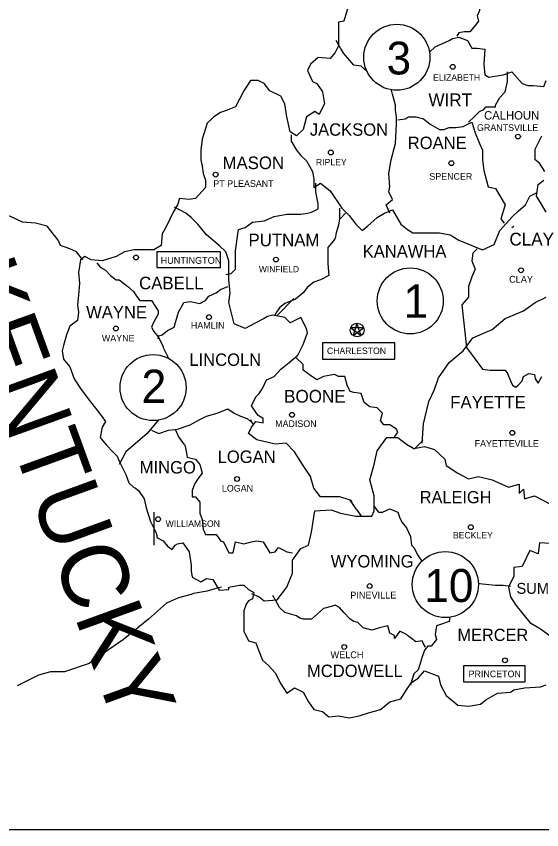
# Model space of a CAD drawing. Extents: x -2.1 to 5.9, y -23.5 to -12.8.
# Drawn here: x 2.655 to 3.484, y -23.135 to -21.85 of the extents above; entities that cross this region are included whole.
import ezdxf

# ---------------------------------------------------------------- set-up
doc = ezdxf.new("R2010")
doc.units = 0
doc.layers.add('Construction Line', color=7, linetype='Continuous')

msp = doc.modelspace()

# ---------------------------------------------------------------- linework, layer by layer
at = {"layer": 'Construction Line'}
for p, q in [((3.1659, -22.1692), (3.1742, -22.161)), ((3.0655, -22.323), (3.0926, -22.2959)), ((3.2023, -22.3421), (3.1822, -22.3421)), ((3.1822, -22.3421), (3.1986, -22.354)), ((3.1921, -22.335), (3.1861, -22.354)), ((3.1861, -22.354), (3.2023, -22.3421)), ((3.1986, -22.354), (3.1921, -22.335)), ((3.2824, -22.5335), (3.2961, -22.5198)), ((2.8714, -22.633), (2.8714, -22.6851)), ((5.62, -23.1348), (-1.8802, -23.1348))]:
    msp.add_line(p, q, dxfattribs=at)
for points in [[(3.3394, -21.7539), (3.3411, -21.759), (3.3394, -21.7695), (3.3479, -21.7712), (3.3578, -21.7746), (3.3666, -21.7865), (3.37, -21.7865), (3.3785, -21.7933), (3.3836, -21.8117), (3.3853, -21.8304), (3.3853, -21.8406), (3.3819, -21.8491), (3.3836, -21.8576), (3.3785, -21.8644), (3.37, -21.8743), (3.3612, -21.8743), (3.353, -21.876), (3.3496, -21.8811)], [(3.1799, -21.829), (3.1714, -21.8576), (3.1629, -21.8593), (3.1629, -21.8882), (3.1629, -21.8967), (3.1578, -21.9069), (3.1496, -21.9168), (3.1309, -21.9151), (3.119, -21.9253), (3.1139, -21.9355), (3.1221, -21.9528), (3.1289, -21.9559), (3.1377, -21.9695), (3.1411, -21.9882), (3.1343, -22.0001), (3.1326, -22.0052), (3.1255, -22.0001), (3.1122, -22.0086), (3.1071, -22.029), (3.0969, -22.0389), (3.0867, -22.0324), (3.0816, -22.0086), (3.0782, -21.9882), (3.0717, -21.9763), (3.0544, -21.9678), (3.0459, -21.9559), (3.036, -21.9511), (3.0241, -21.9511), (3.0136, -21.9678), (3.0003, -21.993), (2.9901, -21.997), (2.9816, -22.0001)], [(3.2088, -21.9378), (3.1989, -21.9287), (3.187, -21.927), (3.1714, -21.9086), (3.1663, -21.9001), (3.1595, -21.8882)], [(3.3063, -21.9064), (3.3156, -21.8984), (3.3377, -21.8882), (3.3428, -21.8848), (3.353, -21.8831), (3.3666, -21.8882), (3.3734, -21.9001), (3.3819, -21.9001), (3.3938, -21.9018), (3.3921, -21.9253), (3.3938, -21.9426), (3.4003, -21.946), (3.4227, -21.9426), (3.4363, -21.9375), (3.453, -21.9559), (3.4615, -21.9593), (3.47, -21.9593), (3.487, -21.961), (3.4904, -21.9511)], [(3.3683, -22.0171), (3.3768, -22.0086), (3.3853, -22.0001), (3.3921, -21.997), (3.3952, -21.993), (3.4105, -21.993), (3.4105, -21.9902), (3.4176, -21.978), (3.4261, -21.9695), (3.4295, -21.9528), (3.4295, -21.9375)], [(3.2442, -22.161), (3.238, -22.1477), (3.2479, -22.1392), (3.2425, -22.1273), (3.2442, -22.1191), (3.2425, -22.0984), (3.2459, -22.0766), (3.253, -22.0508), (3.2547, -22.0205), (3.2547, -22.0086), (3.253, -21.9981), (3.253, -21.9902), (3.2479, -21.9729), (3.2468, -21.9664)], [(2.9816, -22.0001), (2.9765, -22.0018), (2.9663, -22.0086), (2.9629, -22.012), (2.9558, -22.0188), (2.9476, -22.044), (2.9459, -22.0613), (2.9459, -22.0766), (2.9476, -22.0865), (2.9493, -22.0984), (2.953, -22.1089), (2.953, -22.1205), (2.9374, -22.1375), (2.9272, -22.1392), (2.9122, -22.1375), (2.9088, -22.1477), (2.902, -22.1593), (2.8915, -22.1817), (2.8847, -22.1936), (2.883, -22.212), (2.8714, -22.2188), (2.8578, -22.2188), (2.8405, -22.2188), (2.8255, -22.2222), (2.8119, -22.2293), (2.7901, -22.2361), (2.7728, -22.2344), (2.7629, -22.2293), (2.7561, -22.2344), (2.7527, -22.2545), (2.7544, -22.2715), (2.7527, -22.2902), (2.751, -22.3055), (2.7527, -22.3171), (2.751, -22.3307), (2.7391, -22.3395), (2.734, -22.3531), (2.7289, -22.3698), (2.7269, -22.3783), (2.7289, -22.3916), (2.7391, -22.4038), (2.7459, -22.4225), (2.7561, -22.4378), (2.7694, -22.4565), (2.7816, -22.4718), (2.7884, -22.4803), (2.7952, -22.4902), (2.7901, -22.4987), (2.7867, -22.5154), (2.7884, -22.5171), (2.7969, -22.5276), (2.8068, -22.5378), (2.8136, -22.5446), (2.817, -22.5528), (2.8272, -22.5735), (2.8323, -22.5871), (2.8394, -22.5939), (2.8428, -22.5953), (2.8476, -22.599), (2.8561, -22.6123), (2.8595, -22.6262), (2.8663, -22.648), (2.8748, -22.665), (2.8765, -22.6701), (2.8765, -22.6732), (2.8864, -22.6783), (2.8932, -22.6868), (2.9003, -22.6922), (2.9054, -22.6851), (2.9088, -22.6834), (2.9173, -22.6817), (2.9272, -22.6956), (2.9306, -22.7177), (2.9306, -22.7259), (2.9323, -22.7361), (2.9459, -22.7432), (2.9547, -22.7378), (2.9646, -22.7395), (2.9748, -22.7565), (2.9901, -22.7551), (2.9901, -22.7517), (3.0068, -22.7483), (3.0136, -22.7483), (3.0207, -22.7551), (3.0292, -22.7599), (3.0275, -22.7701), (3.0207, -22.7735), (3.0173, -22.7786), (3.0136, -22.7888), (3.0136, -22.8058), (3.0136, -22.8211), (3.0207, -22.8364), (3.0326, -22.8395), (3.036, -22.8497), (3.0428, -22.867), (3.0527, -22.8752), (3.0629, -22.8871), (3.0717, -22.9041), (3.0816, -22.9191), (3.0935, -22.9106), (3.1071, -22.9174)], [(3.2564, -22.0137), (3.2683, -22.012), (3.2734, -22.0086), (3.285, -22.0086), (3.2969, -22.012), (3.3074, -22.0205), (3.3224, -22.029), (3.3292, -22.029), (3.3377, -22.0256), (3.3479, -22.0256), (3.3595, -22.0239), (3.3734, -22.0171), (3.3785, -22.0341), (3.3853, -22.0508), (3.3904, -22.0613), (3.3904, -22.0766), (3.3921, -22.0933), (3.3989, -22.1191), (3.4105, -22.1222), (3.4261, -22.1477), (3.4193, -22.1698), (3.4244, -22.1766)], [(3.0884, -22.0372), (3.0884, -22.0474), (3.0969, -22.0613), (3.1037, -22.0698), (3.1122, -22.078), (3.1221, -22.095), (3.1238, -22.1072), (3.1238, -22.1205), (3.1343, -22.1134), (3.1496, -22.1256), (3.168, -22.1528), (3.1799, -22.1644), (3.1904, -22.1783), (3.2003, -22.1885), (3.2088, -22.1817), (3.2241, -22.1678), (3.2357, -22.161), (3.2479, -22.1559), (3.2615, -22.1783), (3.2717, -22.1868), (3.2802, -22.1919), (3.3074, -22.1919), (3.3224, -22.1919), (3.3394, -22.1953), (3.353, -22.2035), (3.3734, -22.212), (3.3904, -22.2188), (3.4088, -22.2103), (3.4176, -22.1885), (3.4377, -22.1661), (3.4462, -22.1579), (3.4581, -22.1477), (3.4649, -22.1341), (3.4754, -22.129)], [(3.4887, -22.095), (3.4802, -22.0817), (3.4731, -22.0766), (3.4731, -22.0596), (3.4836, -22.0389)], [(3.4904, -22.1593), (3.4819, -22.1443), (3.4754, -22.1341), (3.4782, -22.1157), (3.487, -22.1089)], [(2.985, -22.2579), (2.9935, -22.2562), (3.0003, -22.2494), (3.0003, -22.2205), (3.0051, -22.1868), (3.0156, -22.1834), (3.0275, -22.1749), (3.0459, -22.1732), (3.0612, -22.1661), (3.0816, -22.1627), (3.0935, -22.1627), (3.1037, -22.1627), (3.1139, -22.161), (3.1204, -22.1593), (3.1309, -22.1542), (3.1309, -22.146), (3.1272, -22.1273), (3.1272, -22.1134)], [(2.7595, -22.2344), (2.7493, -22.2222), (2.7391, -22.2171), (2.7241, -22.212), (2.7207, -22.2035), (2.7034, -22.1817), (2.6847, -22.1766), (2.6643, -22.1749), (2.6456, -22.1661), (2.6323, -22.161), (2.6153, -22.1559), (2.5983, -22.1528), (2.5762, -22.146), (2.566, -22.146), (2.5561, -22.1443), (2.5422, -22.1443)], [(3.1635, -22.6089), (3.1343, -22.6089), (3.1238, -22.5953), (3.119, -22.5769), (3.1071, -22.5596), (3.0935, -22.5378), (3.0802, -22.5242), (3.0629, -22.5259), (3.0343, -22.5191), (3.0207, -22.5089), (3.0258, -22.4987), (3.0326, -22.4902), (3.0442, -22.4919), (3.0442, -22.4851), (3.036, -22.4803), (3.0258, -22.465), (3.0326, -22.4511), (3.0343, -22.4494), (3.0377, -22.446), (3.0428, -22.4378), (3.0493, -22.4242), (3.0612, -22.4191), (3.0717, -22.4072), (3.085, -22.3967), (3.0986, -22.3851), (3.1071, -22.3681), (3.1139, -22.3497), (3.1122, -22.3429), (3.1037, -22.3256), (3.0867, -22.3341), (3.0782, -22.3256), (3.0595, -22.3222), (3.051, -22.3239), (3.0459, -22.3273), (3.0292, -22.3358), (3.0156, -22.3429), (2.9983, -22.3358), (2.9901, -22.3021), (2.9918, -22.2868), (2.9901, -22.2664), (2.9901, -22.2528), (2.9901, -22.2361), (2.985, -22.2222), (2.9748, -22.212), (2.9547, -22.1953), (2.9408, -22.1783), (2.9306, -22.1678), (2.9221, -22.161), (2.904, -22.1514)], [(3.1646, -22.1528), (3.1646, -22.1593), (3.1646, -22.1698), (3.1629, -22.18), (3.1595, -22.1919), (3.1578, -22.2004), (3.1547, -22.2052), (3.1462, -22.2154), (3.1462, -22.2259), (3.1462, -22.2409), (3.1479, -22.2596), (3.1343, -22.2664), (3.1238, -22.2698), (3.1139, -22.278), (3.1071, -22.2868), (3.0952, -22.297), (3.0782, -22.3038), (3.07, -22.3106), (3.0629, -22.3205), (3.0629, -22.3222)], [(3.4363, -22.1834), (3.4394, -22.1817)], [(3.4363, -22.1834), (3.4394, -22.1817)], [(3.3819, -22.2171), (3.3751, -22.2242), (3.3734, -22.2361), (3.3785, -22.2494), (3.3734, -22.2613), (3.3683, -22.2769), (3.3683, -22.2936), (3.3578, -22.3055), (3.3649, -22.3732)], [(2.7816, -22.2392), (2.7867, -22.246), (2.7952, -22.2511), (2.8034, -22.2596), (2.8119, -22.2664), (2.817, -22.2664), (2.8238, -22.2715), (2.8306, -22.2769), (2.8394, -22.2848), (2.8442, -22.2919), (2.8493, -22.2987), (2.8578, -22.2987), (2.868, -22.2987), (2.8782, -22.3154), (2.8782, -22.3205), (2.8714, -22.3324), (2.868, -22.3412), (2.8714, -22.348), (2.8782, -22.3565), (2.8864, -22.3715), (2.8864, -22.3732), (2.8932, -22.3868), (2.8941, -22.3902)], [(2.8782, -22.3596), (2.8796, -22.3548), (2.8847, -22.3531), (2.8932, -22.3463), (2.9037, -22.3412), (2.9105, -22.3171), (2.919, -22.3021), (2.9289, -22.3004), (2.9442, -22.3038), (2.953, -22.2987), (2.9581, -22.2919), (2.9697, -22.2868), (2.9765, -22.2814), (2.9884, -22.2769)], [(3.2952, -22.5242), (3.2969, -22.4936), (3.3057, -22.4582), (3.3142, -22.4392), (3.3207, -22.4208), (3.3377, -22.3967), (3.3595, -22.3783), (3.3751, -22.3579), (3.4054, -22.3446), (3.4261, -22.3273), (3.4547, -22.3154), (3.4731, -22.3021), (3.4904, -22.2936)], [(3.3649, -22.3732), (3.3785, -22.3916), (3.3904, -22.4072), (3.402, -22.4089), (3.4176, -22.4089), (3.4261, -22.4089), (3.4295, -22.414), (3.4343, -22.4259), (3.4377, -22.4327), (3.4428, -22.4358), (3.4462, -22.4327), (3.453, -22.4259), (3.4547, -22.4191), (3.4632, -22.414), (3.472, -22.4157), (3.4731, -22.4225), (3.4782, -22.4293), (3.4836, -22.4191)], [(3.2513, -22.5143), (3.2564, -22.5072), (3.2547, -22.5021), (3.2442, -22.4953), (3.2343, -22.4953), (3.2292, -22.4885), (3.2326, -22.4766), (3.2241, -22.4684), (3.2122, -22.4667), (3.2037, -22.4599), (3.1989, -22.446), (3.187, -22.4443), (3.1816, -22.4426), (3.1765, -22.4327), (3.1731, -22.4191), (3.1629, -22.4191), (3.1564, -22.4157), (3.1394, -22.4191), (3.1289, -22.4242), (3.119, -22.4174), (3.1071, -22.4089), (3.1071, -22.4001), (3.0952, -22.3885)], [(2.868, -22.5038), (2.8796, -22.5089), (2.8949, -22.5038), (2.9088, -22.5021), (2.9289, -22.4953), (2.9442, -22.4868), (2.9547, -22.4817), (2.9714, -22.4766), (2.9884, -22.4701), (2.9983, -22.4766), (3.0085, -22.4817), (3.019, -22.4851), (3.0241, -22.4902)], [(2.879, -22.4871), (2.8612, -22.5089), (2.8272, -22.5378), (2.817, -22.5579)], [(3.0241, -22.4868), (3.0275, -22.4936)], [(3.0241, -22.4868), (3.0275, -22.4936)], [(2.9054, -22.5021), (2.9105, -22.5143), (2.919, -22.5259), (2.9204, -22.5276), (2.9221, -22.5344), (2.9241, -22.5463), (2.9306, -22.548), (2.9374, -22.5497), (2.9442, -22.5579), (2.9476, -22.5715), (2.9408, -22.5803), (2.9357, -22.5888), (2.9323, -22.599), (2.9323, -22.6089), (2.9374, -22.6089), (2.9442, -22.6174), (2.9442, -22.6347), (2.9476, -22.6446), (2.9493, -22.6599), (2.953, -22.6684), (2.9697, -22.6684), (2.9748, -22.6752), (2.9765, -22.6783), (2.9816, -22.68), (2.9901, -22.6973), (2.9969, -22.6973), (3.0003, -22.68), (3.0136, -22.6834), (3.0258, -22.68), (3.0343, -22.6783), (3.0442, -22.68), (3.0544, -22.6973), (3.0629, -22.6956), (3.0683, -22.6888), (3.0745, -22.6922), (3.0816, -22.6956), (3.0901, -22.6973)], [(3.0258, -22.7616), (3.0377, -22.7667), (3.0459, -22.7735), (3.0663, -22.7718), (3.0816, -22.7517), (3.0901, -22.7293), (3.0901, -22.7157), (3.0901, -22.7092), (3.1037, -22.6905), (3.1156, -22.6851), (3.1204, -22.665), (3.1255, -22.6313), (3.1513, -22.6296), (3.1663, -22.6347), (3.1904, -22.6395), (3.2156, -22.6395), (3.219, -22.6313), (3.219, -22.6072), (3.2122, -22.582), (3.219, -22.5579), (3.2241, -22.5361), (3.2391, -22.5154), (3.2564, -22.5154), (3.27, -22.5259), (3.2816, -22.5327), (3.2986, -22.5293), (3.3142, -22.5344), (3.3309, -22.5497), (3.3326, -22.5596), (3.3513, -22.5715), (3.3683, -22.5803), (3.3836, -22.5769), (3.4054, -22.582), (3.4312, -22.5939), (3.4479, -22.5888), (3.4479, -22.6038), (3.4547, -22.597), (3.4564, -22.6123), (3.472, -22.6072), (3.4972, -22.6208)], [(3.1921, -22.6296), (3.1816, -22.614), (3.1635, -22.6086)], [(3.1813, -22.6138), (3.1839, -22.6171)], [(3.219, -22.6242), (3.2258, -22.633), (3.2326, -22.633), (3.2442, -22.6279), (3.2564, -22.633), (3.2598, -22.6429), (3.2632, -22.6497), (3.27, -22.6582), (3.2765, -22.6715), (3.2782, -22.6851), (3.2816, -22.6888), (3.2884, -22.7024), (3.2946, -22.7106)], [(3.1921, -22.6296), (3.1989, -22.6395)], [(3.5057, -22.6834), (3.4802, -22.6817), (3.4782, -22.699), (3.4649, -22.6939), (3.453, -22.7191), (3.4394, -22.7208), (3.4394, -22.7344), (3.4312, -22.7517), (3.4343, -22.7667), (3.4428, -22.7803), (3.4649, -22.8075), (3.4819, -22.8177), (3.5006, -22.8313)], [(2.9782, -22.7517), (2.9714, -22.7534), (2.9558, -22.7582), (2.934, -22.7616), (2.9306, -22.7633), (2.9105, -22.7684), (2.8915, -22.7769), (2.8629, -22.8021), (2.8238, -22.8344), (2.7918, -22.8565), (2.7694, -22.8721), (2.7306, -22.8854), (2.7085, -22.8854), (2.6898, -22.8905), (2.6663, -22.9024), (2.6558, -22.9075)], [(3.3833, -22.7455), (3.3904, -22.7466), (3.4105, -22.7483), (3.4227, -22.7483), (3.4343, -22.75)], [(3.3003, -22.8463), (3.2969, -22.8412), (3.2952, -22.8364), (3.285, -22.8378), (3.2782, -22.8327), (3.2717, -22.8279), (3.27, -22.8262), (3.2598, -22.8211), (3.2513, -22.8327), (3.2513, -22.8279), (3.2442, -22.8245), (3.2408, -22.8126), (3.2275, -22.816), (3.2156, -22.8194), (3.202, -22.816), (3.1935, -22.8075), (3.187, -22.8058), (3.1816, -22.8021), (3.1714, -22.7919), (3.1646, -22.7837), (3.1578, -22.7803), (3.1513, -22.782), (3.1394, -22.7854), (3.1204, -22.8021), (3.119, -22.8021), (3.1071, -22.8021), (3.102, -22.8004), (3.0969, -22.797), (3.0782, -22.7919), (3.07, -22.7837), (3.0663, -22.7769), (3.0595, -22.765)], [(3.3385, -22.7993), (3.3377, -22.8058), (3.3224, -22.8109), (3.3176, -22.8126), (3.3156, -22.8262), (3.3176, -22.8344), (3.3091, -22.8446), (3.304, -22.8446), (3.2986, -22.8514), (3.2952, -22.8619), (3.2918, -22.8721), (3.2884, -22.882), (3.2816, -22.8888), (3.2765, -22.9058)], [(3.1071, -22.9174), (3.1156, -22.933), (3.1238, -22.9449), (3.1377, -22.9483), (3.1479, -22.9565), (3.1629, -22.9551), (3.1799, -22.9582), (3.1955, -22.9551), (3.2105, -22.95), (3.2292, -22.9449), (3.2442, -22.933), (3.2615, -22.9279), (3.27, -22.914), (3.2782, -22.9024), (3.2884, -22.8956), (3.2986, -22.8837), (3.3207, -22.8922), (3.3241, -22.9058), (3.3326, -22.9228), (3.3513, -22.9381), (3.3683, -22.9398), (3.387, -22.9364), (3.3952, -22.9296), (3.4139, -22.9191), (3.4343, -22.9174), (3.4394, -22.914), (3.4564, -22.9106), (3.4819, -22.9089), (3.4904, -22.9058)]]:
    msp.add_lwpolyline(points, dxfattribs=at)
for points in [[(2.9768, -22.2222), (2.8762, -22.2222), (2.8762, -22.2466), (2.9768, -22.2466)], [(3.1377, -22.3659), (3.1377, -22.3914), (3.2516, -22.3914), (3.2516, -22.3659)], [(3.3604, -22.8758), (3.3604, -22.901), (3.4573, -22.901), (3.4573, -22.8758)]]:
    msp.add_lwpolyline(points, close=True, dxfattribs=at)
for centre, radius in [((3.255, -21.9147), 0.0521), ((3.3432, -21.9298), 0.00381), ((3.4461, -22.0399), 0.00381), ((3.1509, -22.0651), 0.00381), ((3.3411, -22.082), 0.00381), ((2.9691, -22.1), 0.00381), ((2.8434, -22.231), 0.00381), ((3.0642, -22.2342), 0.00381), ((3.2761, -22.2995), 0.0521), ((3.451, -22.2511), 0.00381), ((2.9586, -22.3251), 0.00381), ((2.8117, -22.343), 0.00381), ((3.1924, -22.3455), 0.0108), ((2.8703, -22.4365), 0.0521), ((3.0896, -22.4794), 0.00381), ((3.4373, -22.5079), 0.00381), ((3.0029, -22.5808), 0.00381), ((2.8783, -22.6442), 0.00381), ((3.3717, -22.6569), 0.00381), ((3.3315, -22.7475), 0.0521), ((3.2122, -22.7499), 0.00381), ((3.172, -22.8461), 0.00381), ((3.4256, -22.8672), 0.00381)]:
    msp.add_circle(centre, radius, dxfattribs=at)

# ---------------------------------------------------------------- texts
for s, height, p in [('3', 0.0518, (3.2389, -21.9418)), ('ELIZABETH', 0.0102, (3.3122, -21.9517)), ('WIRT', 0.02011, (3.3049, -21.9919)), ('CALHOUN', 0.01331, (3.3926, -22.0131)), ('JACKSON', 0.01955, (3.1177, -22.0386)), ('GRANTSVILLE', 0.010481, (3.3815, -22.031)), ('ROANE', 0.01955, (3.2722, -22.0596)), ('MASON', 0.01983, (2.9799, -22.0913)), ('RIPLEY', 0.0102, (3.1273, -22.0854)), ('SPENCER', 0.01048, (3.3063, -22.1081)), ('PT PLEASANT', 0.010481, (2.9655, -22.1194)), ('PUTNAM', 0.01983, (3.0209, -22.2132)), ('CLAY', 0.02011, (3.4327, -22.212)), ('KANAWHA', 0.01955, (3.2011, -22.231)), ('HUNTINGTON', 0.01076, (2.8822, -22.2409)), ('WINFIELD', 0.00991, (3.0374, -22.2542)), ('CABELL', 0.01983, (2.8483, -22.2812)), ('CLAY', 0.01076, (3.4322, -22.2707)), ('1', 0.0527, (3.2654, -22.3262)), ('WAYNE', 0.01955, (2.7648, -22.327)), ('HAMLIN', 0.01048, (2.9301, -22.3435)), ('WAYNE', 0.01048, (2.7896, -22.3636)), ('LINCOLN', 0.01955, (2.9276, -22.4021)), ('CHARLESTON', 0.0102, (3.1447, -22.3834)), ('2', 0.0527, (2.8521, -22.4608)), ('BOONE', 0.02011, (3.0771, -22.4602)), ('FAYETTE', 0.01983, (3.3392, -22.4693)), ('MADISON', 0.01048, (3.063, -22.4987)), ('FAYETTEVILLE', 0.010481, (3.3778, -22.5299)), ('LOGAN', 0.01955, (2.9722, -22.5554)), ('MINGO', 0.01955, (2.8493, -22.5721)), ('LOGAN', 0.01048, (2.979, -22.6007)), ('RALEIGH', 0.01926, (3.2912, -22.6191)), ('WILLIAMSON', 0.0102, (2.8902, -22.6565)), ('BECKLEY', 0.0102, (3.3435, -22.6747)), ('WYOMING', 0.01955, (3.1507, -22.7205)), ('10', 0.05213, (3.2983, -22.7752)), ('SUMMERS', 0.01728, (3.4437, -22.7622)), ('PINEVILLE', 0.01076, (3.1815, -22.7696)), ('MERCER', 0.01926, (3.3507, -22.8367)), ('WELCH', 0.01076, (3.1504, -22.8639)), ('MCDOWELL', 0.01955, (3.1132, -22.8936)), ('PRINCETON', 0.01048, (3.3682, -22.8939))]:
    msp.add_text(s, height=height, dxfattribs=at).set_placement(p)
msp.add_text('KENTUCKY', height=0.10489, rotation=289.9831, dxfattribs=at).set_placement((2.5489, -22.2553))

doc.saveas('drawing.dxf')
